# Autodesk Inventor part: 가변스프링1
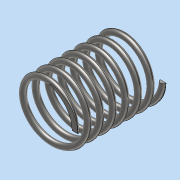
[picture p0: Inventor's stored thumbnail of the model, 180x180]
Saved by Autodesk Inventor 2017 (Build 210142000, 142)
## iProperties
Part Number: 가변스프링1
Material: 스테인레스 스틸
Document SubType Name: Modeling
Designer: MRC
Density: 8 g/cm^3
Appearance: 반연마
Mass: 10.8942 g
Surface Area: 27.565 cm^2
Volume: 1.36177 cm^3
Author: MRC
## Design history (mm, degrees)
sketch "스케치1"
  geometry: L1 (0, 0)-(10, 0); L2 (10, 0)-(10, 30.358); L3 (10, 30.358)-(0, 30.358); L4 (0, 30.358)-(0, 0); C1 r 1 at (10, 0)
  constraints: 8 end point, 2 parallel, 1 centre point, 1 coincident, 1 horizontal, 1 perpendicular
  dimensions: "d0" = 30.35829 distance of L3.end L1.start (derived); "d1" = 20 diameter of L2 L4; "d2" = 2 diameter of C1
feature "코일1" sketch "스케치1" pitch "d3" = 10; turns "d5" = 7; dims "d4" = 30.35829 (= d0), "d6" = 0, angle "d7" = 90 deg, angle "d8" = 90 deg, "d9" = 0, "d10" = 0
sketch "스케치2"
  geometry: L1 (-20, 30.358)-(20, 30.358); L2 (20, 30.358)-(20, 0); L3 (20, 0)-(-20, 0); L4 (-20, 0)-(-20, 30.358); L5 (0, 30.358)-(0, 0) reference; 2 further points
  constraints: 8 end point, 2 midpoint, 2 parallel, 1 coincident, 1 horizontal, 1 perpendicular
  dimensions: "d11" = 40 distance of L1.start L1.end
extrude "돌출1" sketch "스케치2" stored distance "d12" = 0; taper "d13" = 0 deg
node "솔리드1"
